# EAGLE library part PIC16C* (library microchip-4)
MICROCONTROLLER PIC16C5X family: EPROM/ROM-based PIC16C55X family: EPROM-based PIC16C6X family PIC16CE62X family: analog comparators/EEPROM data memory PIC16C7X family: A/D converter PIC16C71X family: A/D converter PIC16F8X family: flash EEPROM Pin compatible devices: PIC16C154, PIC16CR154, PIC16C156, PIC16CR156, PIC16C158 PIC16CR158, PIC16C52, PIC16C54, PIC16C54A, PIC16CR54A PIC16C56, PIC16C58A, PIC16CR58A, PIC16C61, PIC16C554 PIC16C556, PIC16C558, PIC16C620, PIC16C621, PIC16C622 PIC16C641, PIC16C642, PIC16C661, PIC16C662, PIC16C71 PIC16C710, PIC16C711, PIC16C715, PIC126F83, PIC16CR83 PIC16F84A, PIC16CR84 see also PIC16F8*
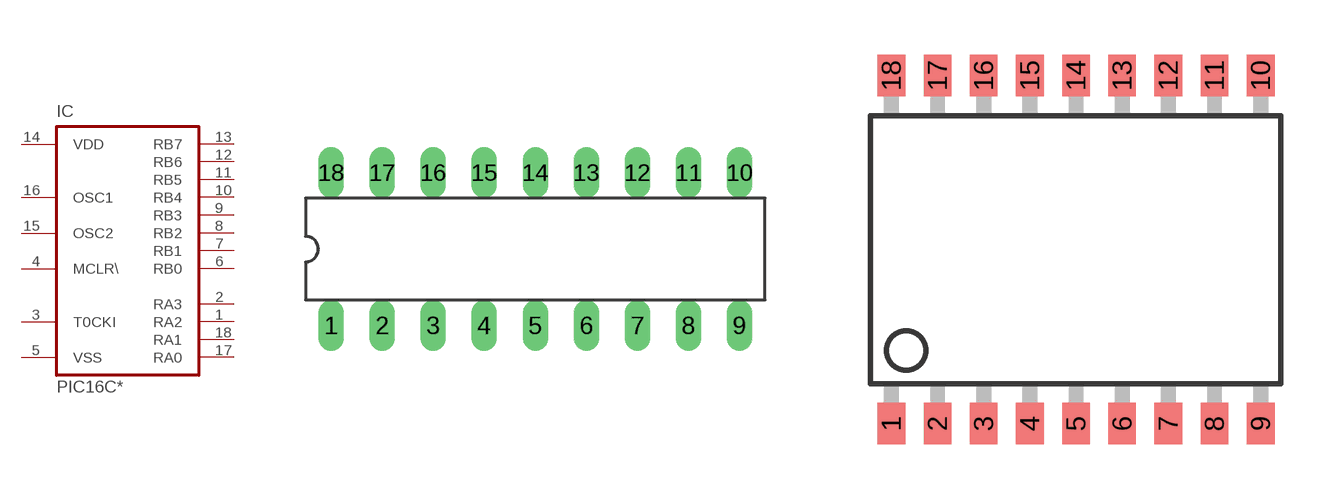
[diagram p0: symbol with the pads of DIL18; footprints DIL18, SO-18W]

Designator prefix IC

## PIC16C154P, PIC16C156P, PIC16C158P, PIC16C52P, PIC16C54P, PIC16C54AP, PIC16C55P, PIC16C554P, PIC16C556P, PIC16C558P, PIC16C56P, PIC16C58AP, PIC16C61P, PIC16C620P, PIC16C621P, PIC16C622P, PIC16C641P, PIC16C661P, PIC16C71P, PIC16C710P, PIC16C711P, PIC16C715P, PIC16C84P, PIC16CF83P, PIC16CR154P, PIC16CR156P, PIC16CR158P, PIC16CR54P, PIC16CR54AP, PIC16CR58AP, PIC16CR83P, PIC16CR84P  [DIL18]
1  RA2
2  RA3
3  T0CKI  in
4  MCLR\  in
5  VSS  pwr
6  RB0
7  RB1
8  RB2
9  RB3
10  RB4
11  RB5
12  RB6
13  RB7
14  VDD  pwr
15  OSC2  out
16  OSC1  in
17  RA0
18  RA1

## PIC16C154SO, PIC16C156SO, PIC16C158SO, PIC16C52SO, PIC16C54SO, PIC16C54ASO, PIC16C55SO, PIC16C554SO, PIC16C556SO, PIC16C558SO, PIC16C58ASO, PIC16C61SO, PIC16C620SO, PIC16C621SO, PIC16C622SO, PIC16C71SO, PIC16C710SO, PIC16C711SO, PIC16C715SO, PIC16C84SO, PIC16CR154SO, PIC16CR156SO, PIC16CR158SO, PIC16CR54SO, PIC16CR54ASO, PIC16CR58ASO, PIC16CR83SO, PIC16CR84SO  [SO-18W]
Pads as for DIL18

## Footprint DIL18 (pad centres in mm)
Dual In Line package type P
drill 0.5 pad 1.27 long: 1 -10.16,-3.81; 2 -7.62,-3.81; 3 -5.08,-3.81; 4 -2.54,-3.81; 5 0,-3.81; 6 2.54,-3.81; 7 5.08,-3.81; 8 7.62,-3.81; 9 10.16,-3.81; 10 10.16,3.81; 11 7.62,3.81; 12 5.08,3.81; 13 2.54,3.81; 14 0,3.81; 15 -2.54,3.81; 16 -5.08,3.81; 17 -7.62,3.81; 18 -10.16,3.81

## Footprint SO-18W (pad centres in mm)
Small Outline Wide Plastic Gull Wing 300-mil body, package type SO
smd 0.762 x 1.143: 1 -5.08,-4.788; 2 -3.81,-4.788; 3 -2.54,-4.788; 4 -1.27,-4.788; 5 0,-4.788; 6 1.27,-4.788; 7 2.54,-4.788; 8 3.81,-4.788; 9 5.08,-4.788; 10 5.08,4.788; 11 3.81,4.788; 12 2.54,4.788; 13 1.27,4.788; 14 0,4.788; 15 -1.27,4.788; 16 -2.54,4.788; 17 -3.81,4.788; 18 -5.08,4.788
